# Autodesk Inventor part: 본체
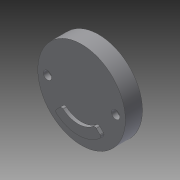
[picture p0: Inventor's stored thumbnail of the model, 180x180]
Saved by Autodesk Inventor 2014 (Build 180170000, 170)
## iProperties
Created: 2015-04
Part Number: 본체
Material: 일반
Document SubType Name: Modeling
Designer: basic
Density: 1 g/cm^3
Appearance: 기본값
Author: basic
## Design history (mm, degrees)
sketch "스케치1"
  geometry: C1 r 95 at (0, 0); 1 further point
  constraints: 1 centre point, 1 coincident
  dimensions: "d0" = 190 diameter of C1
extrude "돌출1" new body sketch "스케치1" distance "d1" = 37; taper "d2" = 0 deg
sketch "스케치2"
  geometry: L1 (47.117, 12)-(76.916, 12); L2 (-76.916, 12)-(-47.117, 12); C1 r 95 at (0, 0) reference; A1 r 90 centre (0, 0) between (86.53, 24.75) and (-86.53, 24.75); A2 r 42 centre (0, 0) between (38.056, 17.769) and (-38.056, 17.769); A3 r 10 centre (-47.117, 22) between (-47.117, 12) and (-38.056, 17.769); A4 r 10 centre (47.117, 22) between (38.056, 17.769) and (47.117, 12); A5 r 10 centre (-76.916, 22) between (-86.53, 24.75) and (-76.916, 12); A6 r 10 centre (76.916, 22) between (76.916, 12) and (86.53, 24.75)
  constraints: 12 point on circle, 12 tangent, 6 centre point, 4 end point, 3 equal radius, 2 coincident, 2 horizontal
  dimensions: "d3" = 180 diameter of A1; "d5" = 84 diameter of A2; "d6" = 20 diameter of A4; "d7" = 12 distance from line of C1.centre L2
extrude "돌출2" cut sketch "스케치2" distance "d8" = 25; taper "d9" = 0 deg
sketch "스케치4"
  geometry: L1 (76.916, 12)-(47.117, 12) reference; L2 (-47.117, 12)-(-76.916, 12) reference; C1 r 95 at (0, 0) reference; C2 r 90 at (0, 0); A1 r 10 centre (76.916, 22) between (76.916, 12) and (86.53, 24.75) reference; A2 r 10 centre (47.117, 22) between (38.056, 17.769) and (47.117, 12) reference; A3 r 42 centre (0, 0) between (38.056, 17.769) and (-38.056, 17.769) reference; A4 r 10 centre (-47.117, 22) between (-47.117, 12) and (-38.056, 17.769) reference; A5 r 10 centre (-76.916, 22) between (-86.53, 24.75) and (-76.916, 12) reference; A6 r 90 centre (0, 0) between (86.53, 24.75) and (-86.53, 24.75) reference
  constraints: 1 centre point, 1 coincident
  dimensions: "d22" = 180 diameter of C2
extrude "돌출3" cut sketch "스케치4" distance "d23" = 10; taper "d24" = 0 deg
sketch "스케치6"
  geometry: L1 (0, 0)-(0, 107.953); L2 (0, 0)-(50.912, 50.912); L3 (0, 0)-(-50.912, 50.912); C1 r 95 at (0, 0) reference; A1 r 51 centre (0, 0) between (36.062, 36.062) and (-36.062, 36.062); A2 r 72 centre (0, 0) between (50.912, 50.912) and (-50.912, 50.912)
  constraints: 6 end point, 4 point on circle, 2 centre point, 2 coincident, 2 point on line, 1 vertical
  dimensions: "d36" = 102 diameter of A1; "d37" = 144 diameter of A2; "d38" = 45 deg angle of L1 L2; "d41" = 90 deg angle of L3 L2
extrude "돌출5" join sketch "스케치6" distance "d42" = 7.5; taper "d43" = 0 deg
fillet "모깎기1" dims "d44" = 5
sketch "스케치7"
  geometry: C1 r 15 at (-40, 52); C2 r 15 at (40, 52); A1 r 90 centre (0, 0) between (86.53, 24.75) and (-86.53, 24.75) reference
  constraints: 2 centre point, 1 equal radius, 1 horizontal alignment
  dimensions: "d45" = 30 diameter of C1; "d46" = 40 horizontal distance of C1.centre A1.centre; "d47" = 52 vertical distance of A1.centre C1.centre; "d49" = 80 distance of C2.centre C1.centre
extrude "돌출6" join sketch "스케치7" distance "d50" = 32; taper "d51" = 0 deg
sketch "스케치8"
  geometry: C1 r 15 at (0, 0) reference; C2 r 10 at (0, 0); C3 r 15 at (80, 0) reference; C4 r 10 at (80, 0); 1 further point
  constraints: 2 centre point, 2 coincident
  dimensions: "d52" = 20 diameter of C2; "d53" = 20 diameter of C4
extrude "돌출7" cut sketch "스케치8" distance "d54" = 25; taper "d55" = 0 deg
sketch "스케치9"
  geometry: L1 (-6, 20)-(6, 20); L2 (6, 20)-(6, -20); L3 (6, -20)-(-6, -20); L4 (-6, -20)-(-6, 20); L5 (-6, 0)-(6, 0); L6 (74, -20)-(86, -20); L7 (86, -20)-(86, 20); L8 (86, 20)-(74, 20); L9 (74, 20)-(74, -20); L10 (74, 0)-(86, 0); C1 r 10 at (0, 0) reference; C2 r 15 at (80, 0) reference; 3 further points
  constraints: 20 end point, 6 midpoint, 4 parallel, 2 coincident, 2 equal length, 2 horizontal, 2 perpendicular
  dimensions: "d56" = 12 distance of L2.end L3.end; "d57" = 40 distance of L1.end L2.end
extrude "돌출8" cut sketch "스케치9" distance "d58" = 3; taper "d59" = 0 deg
sketch "스케치10"
  geometry: C1 r 9 at (74, 0); C2 r 9 at (-74, 0); A1 r 51 centre (0, 0) between (32.699, 39.138) and (-32.699, 39.138) reference
  constraints: 2 centre point, 2 horizontal alignment, 1 equal radius
  dimensions: "d60" = 18 diameter of C1; "d61" = 74 distance of C1.centre A1.centre; "d62" = 148 distance of C2.centre C1.centre
extrude "돌출9" cut sketch "스케치10" distance "d63" = 11; taper "d64" = 0 deg
node "솔리드1"
other parameters: "d4" = 12, "d14" = 82, "d16" = 118, "d26" = 118, "d28" = 5
